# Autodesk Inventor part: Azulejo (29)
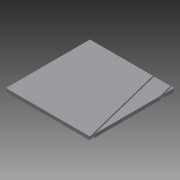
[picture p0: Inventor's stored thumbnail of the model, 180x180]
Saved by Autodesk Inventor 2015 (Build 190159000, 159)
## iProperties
Created: 2015-04
Part Number: Azulejo (29)
Material: Genérico
Document SubType Name: Modeling
Designer: Felipe
Density: 1 g/cm^3
Appearance: Padrão
Author: Felipe
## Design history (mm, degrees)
sketch "Sketch1"
  geometry: L1 (-1510, -7490)-(-1510, -6010); L2 (-3010, -1490)-(-3010, -10); L3 (-2990, 10)-(-1510, 10); L4 (-1510, -10)-(-2990, -10); L5 (-1510, -1490)-(-1510, -10); L6 (-1490, -10)-(-1490, -1490); L7 (-1490, -1490)-(-10, -1490); L8 (-10, -1510)-(-1490, -1510); L9 (-10, -2990)-(-10, -1510); L10 (-10, -5990)-(-10, -4510); L11 (-1490, -7490)-(-10, -7490); L12 (4490, -6010)-(3010, -6010); L13 (10, -1510)-(10, -2990); L14 (10, -3010)-(10, -4490); L15 (10, -4510)-(10, -5990); L16 (10, -5990)-(1490, -5990); L17 (1490, -6010)-(10, -6010); L18 (10, -7490)-(1490, -7490); L19 (1510, -5990)-(2990, -5990); L20 (2990, -6010)-(1510, -6010); L21 (1510, -7490)-(2990, -7490); L22 (4490, 1510)-(4490, 2990); L23 (4490, 10)-(4490, 1490); L24 (4490, -1490)-(4490, -10); L25 (4490, -2990)-(4490, -1510); L26 (3010, -5990)-(4490, -5990); L27 (3010, -7490)-(4490, -7490); L28 (4510, 3010)-(5990, 3010); L29 (5990, 2990)-(4510, 2990); L30 (4510, 2990)-(4510, 1510); L31 (4510, 1510)-(5990, 1510); L32 (5990, 1510)-(5990, 1740.185); L33 (5990, 1760.2)-(5990, 2259.8); L34 (5990, 2279.815)-(5990, 2990); L35 (5990, 1490)-(4510, 1490); L36 (4510, 1490)-(4510, 10); L37 (4510, 10)-(5990, 10); L38 (5990, 10)-(5990, 1490); L39 (5975.983, -10)-(4510, -10); L40 (4510, -10)-(4510, -1490); L41 (5990, -1510)-(5782.897, -1510); L42 (5782.897, -1510)-(5688.66, -1510); L43 (5668.66, -1510)-(5482.895, -1510); L44 (5482.895, -1510)-(5388.656, -1510); L45 (5368.656, -1510)-(4510, -1510); L46 (4510, -1510)-(4510, -2990); L47 (4510, -2990)-(5975.983, -2990); L48 (5990, -2975.728)-(5990, -2837.377); L49 (5990, -2837.377)-(5990, -2536.247); L50 (5990, -2500.476)-(5990, -2317.632); L51 (5990, -2317.632)-(5990, -1510); L52 (5990, -3010)-(4510, -3010); L53 (5990, -4490)-(5990, -3010); L54 (4510, -5990)-(5990, -5990); L55 (5990, -5990)-(5990, -4510); L56 (4510, -7490)-(5990, -7490); L57 (5990, -7490)-(5990, -6310); L58 (5990, -6290)-(5990, -6010); L59 (7490, 4510)-(7490, 5990); L60 (6010, 3010)-(7490, 3010); L61 (7490, 3010)-(7490, 4490); L62 (7490, 2990)-(6010, 2990); L63 (6010, 2990)-(6010, 2279.815); L64 (6010, 2259.8)-(6010, 1760.2)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; A1 r 250 centre (6000, 2010) between (5990, 2259.8) and (5990, 1760.2); A2 r 250 centre (6000, 2010) between (6010, 1760.2) and (6010, 2259.8); A3 r 270 centre (6000, 2010) between (5990, 2279.815) and (5990, 1740.185); A4 r 270 centre (6000, 2010) between (6010, 1740.185) and (6010, 2279.815); A5 r 3010.017 centre (0, 0) between (-1490, -2615.358) and (-346.554, -2990); A6 r 2990.017 centre (0, 0) between (-1490, -2592.316) and (-10, -2990); A7 r 3010.017 centre (0, 0) between (-2603.863, -1510) and (-1510, -2603.863); A8 r 2990.017 centre (0, 0) between (-2580.717, -1510) and (-1510, -2580.717); A9 r 3010.017 centre (0, 0) between (-2990, -346.554) and (-2615.358, -1490); A10 r 2990.017 centre (0, 0) between (-2990, -10) and (-2592.316, -1490); A11 r 2131.367 centre (7500, -1500) between (7490, 631.344) and (6010, 24.017); A12 r 2131.367 centre (7500, -1500) between (5975.983, -10) and (5368.656, -1490); A13 r 2131.367 centre (7500, -1500) between (5368.656, -1510) and (5975.983, -2990); A14 r 2131.367 centre (7500, -1500) between (6010, -3024.017) and (7190, -3608.703); A15 r 1831.367 centre (7500, -1500) between (7490.321, 331.342) and (6463.753, 10); A16 r 1831.367 centre (7500, -1500) between (6435.196, -10) and (6010, -435.196); A17 r 1831.367 centre (7500, -1500) between (5990, -463.753) and (5668.66, -1490); A18 r 1831.367 centre (7500, -1500) between (5668.66, -1510) and (5990, -2536.247); A19 r 1831.367 centre (7500, -1500) between (6010, -2564.804) and (6435.196, -2990); A20 r 1831.367 centre (7500, -1500) between (6463.753, -3010) and (7490, -3331.34); A21 r 2111.367 centre (7500, -1500) between (7490.047, 611.344) and (6024.272, 10); A22 r 2111.367 centre (7500, -1500) between (5990, -24.272) and (5388.656, -1490); A23 r 2111.367 centre (7500, -1500) between (5388.656, -1510) and (5990, -2975.728); A24 r 2111.367 centre (7500, -1500) between (6024.272, -3010) and (7210, -3591.357); A25 r 1811.367 centre (7500, -1500) between (7490.374, 311.342) and (6499.524, 10); A26 r 1811.367 centre (7500, -1500) between (6469.975, -10) and (6010, -469.975); A27 r 1811.367 centre (7500, -1500) between (5990, -499.524) and (5688.66, -1490); A28 r 1811.367 centre (7500, -1500) between (5688.66, -1510) and (5990, -2500.476); A29 r 1811.367 centre (7500, -1500) between (6010, -2530.025) and (6469.975, -2990); A30 r 1811.367 centre (7500, -1500) between (6499.524, -3010) and (7490, -3311.34); A31 r 449.871 centre (7499.449, -4060.672) between (7510, -4510.419) and (7521.546, -4510); 9 further points
  constraints: 698 end point, 64 point on circle, 31 centre point, 11 point on line, 1 other
extrude "Extrusion1" new body sketch "Sketch1" distance "d0" = 60; taper "d1" = 0 deg
extrude "Extrusion2" new body sketch "Sketch1" distance "d2" = 60; taper "d3" = 0 deg
extrude "Extrusion3" new body sketch "Sketch1" distance "d4" = 60; taper "d5" = 0 deg
body "Solid1"
body "Solid2"
body "Solid3"
